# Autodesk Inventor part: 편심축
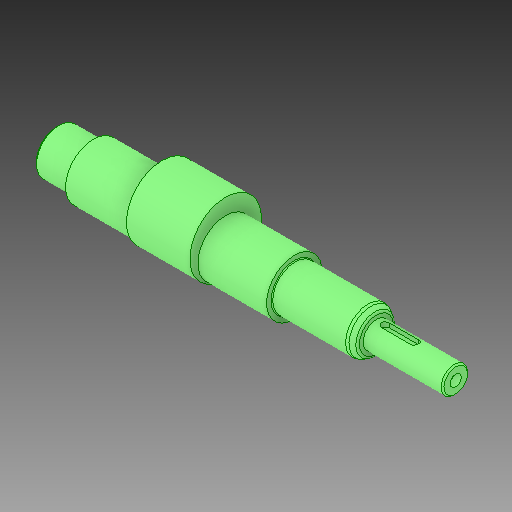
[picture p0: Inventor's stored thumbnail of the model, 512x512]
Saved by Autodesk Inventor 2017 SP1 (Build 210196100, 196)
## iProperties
Created: 2024-09
Part Number: 편심축
Material: 일반
Document SubType Name: Modeling
Designer: MRC
Density: 1 g/cm^3
Appearance: 기본값
Author: jhkim
Sending System: Autodesk Inventor 2025
Preprocessor: ST-DEVELOPER v20
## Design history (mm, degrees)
feature "솔리드1"
node "솔리드2"
